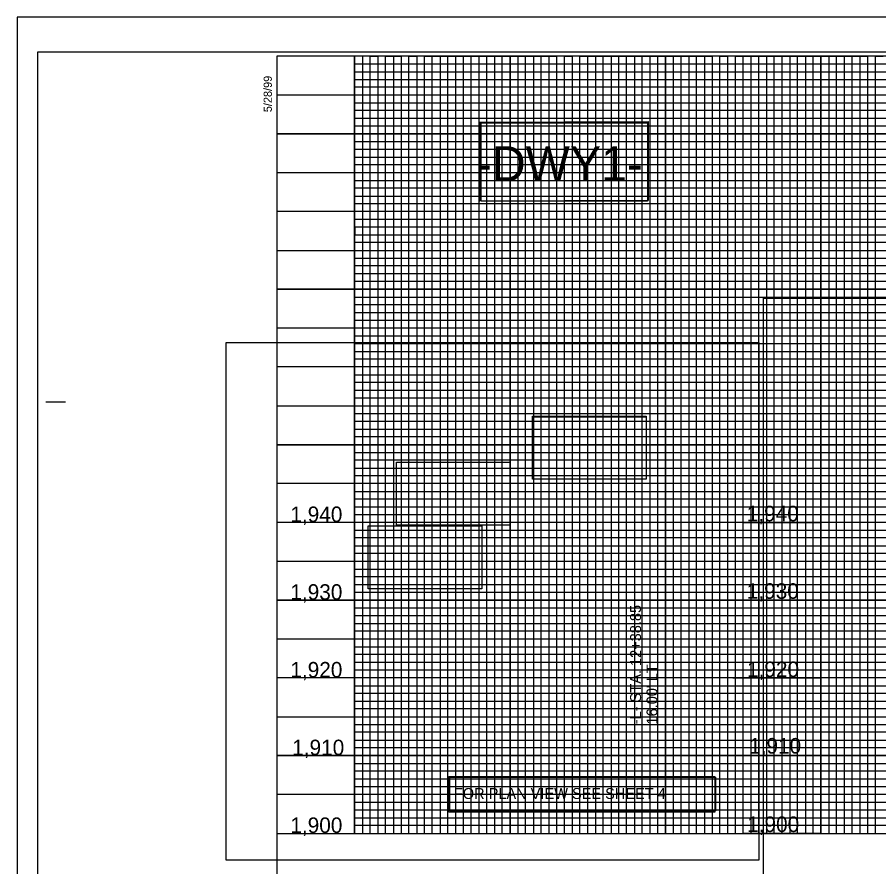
# Model space of a CAD drawing. Extents: x 557032 to 558930, y 525869 to 527437.
# Drawn here: x 557032 to 557587, y 526423 to 526969 of the extents above; entities that cross this region are included whole.
import ezdxf

# ---------------------------------------------------------------- set-up
doc = ezdxf.new("R2010")
doc.units = 0
for name, color, linetype in [('Exist Vertical Profile Vertical Axis Label', 7, 'Continuous'), ('Old_Level_63', 7, 'Continuous'), ('Prop Vertical Profile Curve Label', 7, 'Continuous'), ('Prop Vertical Profile Grade Label', 7, 'Continuous'), ('Prop VPI Label', 7, 'Continuous'), ('Raster_Level_4', 7, 'Continuous'), ('Sheet Cutting Line CELL', 7, 'Continuous'), ('Sheet DOT Grid CELL', 7, 'Continuous'), ('Sheet Layout Profile Border Port 1', 7, 'Continuous'), ('Sheet Plot Border Inside CELL', 7, 'Continuous'), ('Sheet Plot Border Outside CELL', 7, 'Continuous'), ('Sheet Profile CELL', 7, 'Continuous'), ('Sheet Profile Grid Major CELL', 7, 'Continuous'), ('Sheet Profile Grid Middle CELL', 7, 'Continuous'), ('Sheet Profile Grid Minor CELL', 7, 'Continuous')]:
    doc.layers.add(name, color=color, linetype=linetype)

msp = doc.modelspace()

# ---------------------------------------------------------------- linework, layer by layer
at = {"layer": 'Old_Level_63'}
msp.add_lwpolyline([(557499.45, 526794.22), (557549.45, 526794.22), (557549.45, 526444.22), (557499.45, 526444.22)], close=True, dxfattribs=at)
at = {"layer": 'Prop Vertical Profile Curve Label'}
for points in [[(557330.94, 526901.24), (557437.83, 526901.24), (557437.83, 526850.91), (557330.94, 526850.91)], [(557364.01, 526712.06), (557437.07, 526712.06), (557437.07, 526672.14), (557364.01, 526672.14)], [(557276.38, 526682.9), (557349.44, 526682.9), (557349.44, 526642.51), (557276.38, 526642.51)], [(557258.18, 526642.01), (557331.24, 526642.01), (557331.24, 526601.61), (557258.18, 526601.61)]]:
    msp.add_lwpolyline(points, close=True, dxfattribs=at)
at = {"layer": 'Prop VPI Label'}
for points in [[(557330.02, 526901.64), (557438.25, 526902.09), (557438.25, 526851.36), (557330.02, 526850.91)], [(557364.01, 526712.54), (557437.07, 526712.54), (557437.07, 526672.14), (557364.01, 526672.14)], [(557276.38, 526682.9), (557349.44, 526682.9), (557349.44, 526642.51), (557276.38, 526642.51)], [(557258.18, 526642.01), (557331.24, 526642.01), (557331.24, 526601.61), (557258.18, 526601.61)], [(557310.15, 526480.78), (557481.28, 526480.78), (557481.28, 526457.86), (557310.15, 526457.86)], [(557310.65, 526480.31), (557481.61, 526480.31), (557481.61, 526458.69), (557310.65, 526458.69)]]:
    msp.add_lwpolyline(points, close=True, dxfattribs=at)
at = {"layer": 'Raster_Level_4'}
for points in [[(557512.44, 526788.54), (557922.28, 526788.54), (557922.28, 526375.72), (557512.44, 526375.72)], [(557166.79, 526759.89), (557509.5, 526759.89), (557509.5, 526426.94), (557166.79, 526426.94)]]:
    msp.add_lwpolyline(points, close=True, dxfattribs=at)
at = {"layer": 'Sheet Cutting Line CELL'}
for p, q in [((558716.45, 526969.22), (557032.45, 526969.22)), ((557032.45, 526969.22), (557032.45, 525869.22))]:
    msp.add_line(p, q, dxfattribs=at)
at = {"layer": 'Sheet DOT Grid CELL'}
for p, q in [((557249.45, 526444.22), (557249.45, 526944.22)), ((557299.45, 526444.22), (557299.45, 526944.22)), ((557349.45, 526444.22), (557349.45, 526944.22)), ((557399.45, 526444.22), (557399.45, 526944.22)), ((557449.45, 526444.22), (557449.45, 526944.22)), ((557499.45, 526444.22), (557499.45, 526944.22)), ((557549.45, 526444.22), (557549.45, 526944.22)), ((558499.4, 526894.22), (557199.45, 526894.22)), ((558499.4, 526844.22), (557199.45, 526844.22)), ((558499.45, 526794.22), (557199.45, 526794.22)), ((558699.45, 526694.22), (557199.45, 526694.22)), ((558699.45, 526644.22), (557199.45, 526644.22)), ((558699.45, 526594.22), (557199.45, 526594.22)), ((558699.45, 526544.22), (557199.45, 526544.22)), ((558699.45, 526494.22), (557199.45, 526494.22))]:
    msp.add_line(p, q, dxfattribs=at)
at = {"layer": 'Sheet Layout Profile Border Port 1'}
msp.add_lwpolyline([(557249.45, 526783.17), (557249.45, 526444.22), (558649.45, 526444.22), (558649.45, 526783.17)], dxfattribs=at)
at = {"layer": 'Sheet Plot Border Inside CELL'}
msp.add_lwpolyline([(557045.45, 525891.67), (558711.95, 525891.67), (558711.95, 526946.77), (557045.45, 526946.77)], close=True, dxfattribs=at)
at = {"layer": 'Sheet Plot Border Outside CELL'}
msp.add_lwpolyline([(557032.45, 525869.22), (558716.45, 525869.22), (558716.45, 526969.22), (557032.45, 526969.22)], close=True, dxfattribs=at)
at = {"layer": 'Sheet Profile CELL'}
for p, q in [((557050.95, 526721.72), (557063.45, 526721.72)), ((557199.45, 526444.22), (558699.45, 526444.22))]:
    msp.add_line(p, q, dxfattribs=at)
msp.add_lwpolyline([(558699.45, 526944.22), (557199.45, 526944.22), (557199.45, 525894.22), (558699.45, 525894.22)], close=True, dxfattribs=at)
at = {"layer": 'Sheet Profile Grid Major CELL'}
for p, q in [((557499.45, 526644.22), (557549.45, 526644.22)), ((557492.68, 526594.22), (557549.45, 526594.22)), ((557492.68, 526544.22), (557549.45, 526544.22)), ((557542.68, 526544.22), (557542.68, 526544.22)), ((557492.68, 526494.22), (557549.45, 526494.22))]:
    msp.add_line(p, q, dxfattribs=at)
for points in [[(557249.45, 526944.22), (557249.45, 526444.22), (557299.45, 526444.22), (557299.45, 526944.22), (557349.45, 526944.22), (557349.45, 526444.22), (557399.45, 526444.22), (557399.45, 526944.22), (557449.45, 526944.22), (557449.45, 526444.22), (557499.45, 526444.22), (557499.45, 526944.22), (557549.45, 526944.22), (557549.45, 526444.22), (557599.45, 526444.22)], [(557199.45, 526894.22), (558499.45, 526894.22)], [(558499.45, 526844.22), (557199.45, 526844.22), (557199.45, 526794.22), (558499.45, 526794.22)], [(558699.45, 526744.22), (557199.45, 526744.22), (557199.45, 526694.22), (558699.45, 526694.22)], [(558699.45, 526644.22), (557199.45, 526644.22), (557199.45, 526594.22), (558699.45, 526594.22)], [(558699.45, 526544.22), (557199.45, 526544.22), (557199.45, 526544.22), (557199.45, 526494.22), (558699.45, 526494.22)]]:
    msp.add_lwpolyline(points, dxfattribs=at)
at = {"layer": 'Sheet Profile Grid Middle CELL'}
msp.add_line((557199.45, 526919.22), (558499.4, 526919.22), dxfattribs=at)
for points in [[(557274.45, 526944.22), (557274.45, 526444.22), (557324.45, 526444.22), (557324.45, 526944.22), (557374.45, 526944.22), (557374.45, 526444.22), (557424.45, 526444.22), (557424.45, 526944.22), (557474.45, 526944.22), (557474.45, 526444.22), (557524.45, 526444.22), (557524.45, 526944.22), (557574.45, 526944.22), (557574.45, 526444.22), (557624.45, 526444.22)], [(558499.45, 526869.22), (557199.45, 526869.22), (557199.45, 526819.22), (558499.45, 526819.22)], [(558699.45, 526769.22), (557199.45, 526769.22), (557199.45, 526719.22), (558524.45, 526719.22)], [(558699.45, 526669.22), (557199.45, 526669.22), (557199.45, 526619.22), (558699.45, 526619.22)], [(558699.45, 526569.22), (557199.45, 526569.22), (557199.45, 526519.22), (558699.45, 526519.22)], [(558699.45, 526469.22), (557199.45, 526469.22)]]:
    msp.add_lwpolyline(points, dxfattribs=at)
at = {"layer": 'Sheet Profile Grid Minor CELL'}
for p, q in [((557249.45, 526939.22), (558499.45, 526939.22)), ((557249.45, 526934.22), (557249.45, 526934.22)), ((558499.45, 526934.22), (557249.45, 526933.87)), ((557249.45, 526929.22), (558499.45, 526929.22)), ((558499.4, 526809.22), (557249.45, 526809.22)), ((558499.45, 526804.22), (557249.45, 526804.22)), ((558499.45, 526799.22), (557249.45, 526799.22)), ((557249.45, 526789.22), (558499.45, 526789.22)), ((558499.45, 526784.22), (557249.45, 526784.22)), ((557249.45, 526779.22), (558649.45, 526779.22)), ((558649.45, 526759.22), (557249.45, 526759.22)), ((557249.45, 526754.22), (558649.45, 526754.22)), ((558649.45, 526734.22), (557249.45, 526734.22)), ((557249.45, 526729.22), (558649.45, 526729.22)), ((558649.45, 526709.22), (557249.45, 526709.22)), ((557249.45, 526704.22), (558649.45, 526704.22)), ((558649.45, 526699.22), (557249.45, 526699.22)), ((557249.45, 526689.22), (558649.45, 526689.22)), ((558649.45, 526684.22), (557249.45, 526684.22)), ((557249.45, 526679.22), (558649.45, 526679.22)), ((558649.45, 526674.22), (557249.45, 526674.22)), ((557249.45, 526664.22), (558649.45, 526664.22)), ((558649.45, 526659.22), (557249.45, 526659.22)), ((557249.45, 526654.22), (558649.45, 526654.22)), ((558649.45, 526649.22), (557249.45, 526649.22)), ((557249.45, 526639.22), (558649.45, 526639.22)), ((558649.45, 526634.22), (557249.45, 526634.22)), ((557249.45, 526629.22), (558649.45, 526629.22)), ((558649.45, 526624.22), (557249.45, 526624.22)), ((557249.45, 526614.22), (558649.45, 526614.22)), ((558649.45, 526609.22), (557249.45, 526609.22)), ((557249.45, 526604.22), (558649.45, 526604.22)), ((558649.45, 526599.22), (557249.45, 526599.22)), ((557249.45, 526589.22), (558649.45, 526589.22)), ((558649.45, 526584.22), (557249.45, 526584.22)), ((557249.45, 526579.22), (558649.45, 526579.22)), ((558649.45, 526574.22), (557249.45, 526574.22)), ((557249.45, 526564.22), (558649.45, 526564.22)), ((558649.45, 526559.22), (557249.45, 526559.22)), ((558649.45, 526554.22), (557249.45, 526554.22)), ((558649.45, 526549.22), (557249.45, 526549.22)), ((557249.45, 526539.22), (558649.45, 526539.22)), ((558649.45, 526534.22), (557249.45, 526534.22)), ((557249.45, 526529.22), (558649.45, 526529.22)), ((558649.45, 526524.22), (557249.45, 526524.22)), ((557249.45, 526514.22), (558649.45, 526514.22)), ((558649.45, 526509.22), (557249.45, 526509.22)), ((557249.45, 526504.22), (558649.45, 526504.22)), ((558649.45, 526499.22), (557249.45, 526499.22)), ((557249.45, 526489.22), (558649.45, 526489.22)), ((558649.45, 526484.22), (557249.45, 526484.22)), ((557249.45, 526479.22), (558649.45, 526479.22)), ((558649.45, 526474.22), (557249.45, 526474.22)), ((557249.45, 526464.22), (558649.45, 526464.22)), ((558649.45, 526459.22), (557249.45, 526459.22)), ((557249.45, 526454.22), (558649.45, 526454.22))]:
    msp.add_line(p, q, dxfattribs=at)
for points in [[(557254.45, 526944.22), (557254.45, 526444.22), (557259.45, 526444.22), (557259.45, 526944.22), (557264.45, 526944.22), (557264.45, 526444.22), (557269.45, 526444.22), (557269.45, 526944.22), (557279.45, 526944.22), (557279.45, 526444.22), (557284.45, 526444.22), (557284.45, 526944.22), (557289.45, 526944.22), (557289.45, 526444.22), (557294.45, 526444.22), (557304.45, 526444.22), (557309.45, 526444.22), (557309.45, 526944.22), (557314.45, 526944.22), (557314.45, 526444.22), (557319.45, 526444.22), (557319.45, 526944.22), (557329.45, 526944.22), (557329.45, 526444.22), (557334.45, 526444.22), (557334.45, 526944.22), (557339.45, 526944.22), (557339.45, 526444.22), (557344.45, 526444.22), (557344.45, 526944.22), (557354.45, 526944.22), (557354.45, 526444.22), (557359.45, 526444.22), (557359.45, 526944.22), (557364.45, 526944.22), (557364.45, 526444.22), (557369.45, 526444.22), (557369.45, 526944.22), (557379.45, 526944.22), (557379.45, 526444.22), (557384.45, 526444.22), (557384.45, 526944.22), (557389.45, 526944.22), (557389.45, 526444.22), (557394.45, 526444.22), (557394.45, 526944.22), (557404.45, 526944.22), (557404.45, 526444.22), (557409.45, 526444.22), (557409.45, 526944.22), (557414.45, 526944.22), (557414.45, 526444.22), (557419.45, 526444.22), (557419.45, 526944.22), (557429.45, 526944.22), (557429.45, 526444.22), (557434.45, 526444.22), (557434.45, 526944.22), (557439.45, 526944.22), (557439.45, 526444.22), (557444.45, 526444.22), (557444.45, 526944.22), (557454.45, 526944.22), (557454.45, 526444.22), (557459.45, 526444.22), (557459.45, 526944.22), (557464.45, 526944.22), (557464.45, 526444.22)], [(557294.45, 526444.22), (557294.45, 526944.22), (557304.45, 526944.22), (557304.45, 526444.22)], [(557464.45, 526444.22), (557469.45, 526444.22), (557469.45, 526944.22), (557479.45, 526944.22), (557479.45, 526444.22), (557484.45, 526444.22), (557484.45, 526944.22), (557489.45, 526944.22), (557489.45, 526444.22), (557494.45, 526444.22), (557494.45, 526944.22), (557504.45, 526944.22), (557504.45, 526444.22), (557509.45, 526444.22), (557509.45, 526944.22), (557514.45, 526944.22), (557514.45, 526444.22), (557519.45, 526444.22), (557519.45, 526944.22), (557529.45, 526944.22), (557529.45, 526444.22), (557534.45, 526444.22), (557534.45, 526944.22), (557539.45, 526944.22), (557539.45, 526444.22), (557544.45, 526444.22), (557544.45, 526944.22), (557554.45, 526944.22), (557554.45, 526444.22), (557559.45, 526444.22), (557559.45, 526944.22), (557564.45, 526944.22), (557564.45, 526444.22), (557569.45, 526444.22), (557569.45, 526944.22), (557579.45, 526944.22), (557579.45, 526444.22), (557584.45, 526444.22), (557584.45, 526944.22), (557589.45, 526944.22)], [(558499.45, 526924.22), (557249.45, 526924.22), (557249.45, 526914.22), (558499.45, 526914.22)], [(558499.4, 526909.22), (557249.45, 526909.22), (557249.45, 526904.22), (558499.45, 526904.22)], [(558499.45, 526899.22), (557249.45, 526899.22), (557249.45, 526889.22), (558499.45, 526889.22)], [(558499.45, 526884.22), (557249.45, 526884.22), (557249.45, 526879.22), (558499.45, 526879.22)], [(558499.45, 526874.22), (557249.45, 526874.22), (557249.45, 526864.22), (558499.45, 526864.22)], [(558499.45, 526859.22), (557249.45, 526859.22), (557249.45, 526854.22), (558499.45, 526854.22)], [(558499.45, 526849.22), (557249.45, 526849.22), (557249.45, 526839.22), (558499.45, 526839.22)], [(558499.45, 526834.12), (557249.55, 526834.12), (557249.55, 526829.22), (558499.45, 526829.22)], [(558499.45, 526824.22), (557249.45, 526824.22), (557249.45, 526814.22), (558499.45, 526814.22)], [(558649.45, 526774.22), (557249.45, 526774.22), (557249.45, 526764.22), (558649.45, 526764.22)], [(558649.45, 526749.22), (557249.45, 526749.22), (557249.45, 526739.22), (558649.45, 526739.22)], [(558649.45, 526724.22), (557249.45, 526724.22), (557249.45, 526714.22), (558649.45, 526714.22)], [(558649.45, 526449.22), (557249.45, 526449.22)]]:
    msp.add_lwpolyline(points, dxfattribs=at)

# ---------------------------------------------------------------- texts
at = {"layer": 'Exist Vertical Profile Vertical Axis Label'}
for s, p in [('1,940', (557208.15, 526644.47)), ('1,940', (557501.76, 526644.93)), ('1,930', (557208.15, 526594.47)), ('1,930', (557501.76, 526595.08)), ('1,920', (557208.15, 526544.47)), ('1,920', (557501.91, 526544.76)), ('1,910', (557209.35, 526494.47)), ('1,910', (557503.26, 526495.54)), ('1,900', (557208.15, 526444.47)), ('1,900', (557502, 526445.06))]:
    msp.add_text(s, height=10, dxfattribs=at).set_placement(p)
at = {"layer": 'Prop Vertical Profile Grade Label'}
msp.add_text('-DWY1-', height=22.5, dxfattribs=at).set_placement((557327.77, 526863.71))
at = {"layer": 'Prop VPI Label'}
for s, p in [('-L- STA. 12+38.85', (557433.73, 526514.42)), ("16.00' LT.", (557444.27, 526514.23))]:
    msp.add_text(s, height=7, rotation=90, dxfattribs=at).set_placement(p)
msp.add_text('FOR PLAN VIEW SEE SHEET 4', height=7, dxfattribs=at).set_placement((557313.36, 526466.34))
at = {"layer": 'Sheet Profile CELL'}
msp.add_text('5/28/99', height=5.25, rotation=90, dxfattribs=at).set_placement((557196.22, 526908.13))

doc.saveas('drawing.dxf')
